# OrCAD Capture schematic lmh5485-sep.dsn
size A
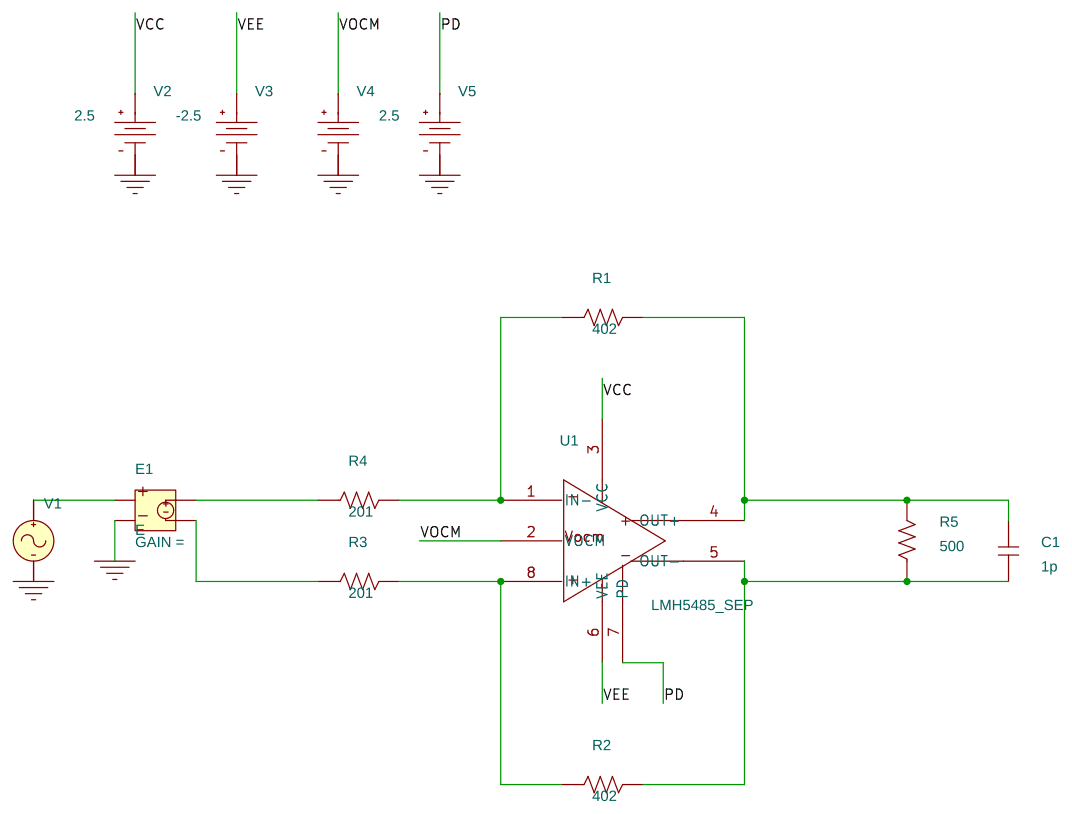
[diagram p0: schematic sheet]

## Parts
C1  1p  [cap196]
E1  E
R1  402  [AXRC05]
R2  402  [AXRC05]
R3  201  [AXRC05]
R4  201  [AXRC05]
R5  500  [AXRC05]
U1  LMH5485_SEP
V1  VAC
V2  VDC
V3  VDC
V4  VDC
V5  VDC

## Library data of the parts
C1 = C
E1 = E
R1-R5 = R
U1 = LMH5485_SEP_0
V1 = VAC
V2 V5 = VDC: DC: 2.5
V3 = VDC: DC: -2.5
V4 = VDC

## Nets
VCC: U1.3(VCC) V2.0(+)
VEE: U1.6(VEE) V3.0(+)
0: E1.2 V1.2(-) V2.1(-) V3.1(-) V4.1(-) V5.1(-)
PD: U1.7(PD) V5.0(+)
VOCM: U1.2(VOCM) V4.0(+)
N01892: R1.1 R4.2 U1.1(IN-)
N01902: C1.2 R1.2 R5.2 U1.4(OUT+)
N02028: E1.1 V1.1(+)
N02034: E1.3 R4.1
N02090: E1.4 R3.1
N02168: C1.1 R2.2 R5.1 U1.5(OUT-)
N02186: R2.1 R3.2 U1.8(IN+)
